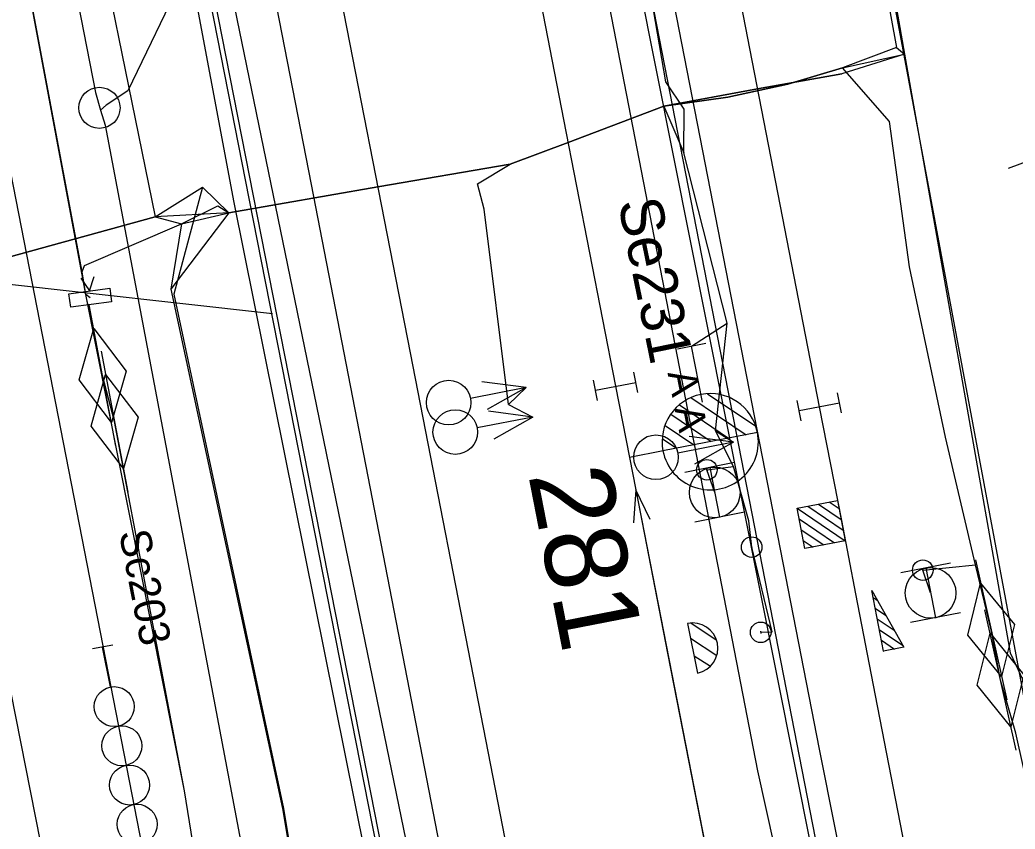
# Model space of a CAD drawing. Extents: x -545846 to -545044, y -1122650 to -1119108.
# Drawn here: x -545690.73 to -545666.54, y -1119398.54 to -1119378.88 of the extents above; entities that cross this region are included whole.
import ezdxf

# ---------------------------------------------------------------- set-up
doc = ezdxf.new("R2010")
doc.units = 0
for name, color, linetype in [('osvětlené plochy-hodnota-obrys', 7, 'Continuous'), ('Vrstva 1', 7, 'Continuous'), ('Vrstva 1 - Koleje', 7, 'Continuous'), ('Vrstva 2 - Vyhybky', 7, 'Continuous'), ('Vrstva 26', 7, 'Continuous'), ('Vrstva 27', 7, 'Continuous'), ('Vrstva 28 - zabzar', 7, 'Continuous'), ('Vrstva 3 - Lisy - Pocitaci body', 7, 'Continuous'), ('Vrstva 31', 7, 'Continuous'), ('Vrstva 32', 7, 'Continuous'), ('Vrstva 33 - prvky sdelzar', 7, 'Continuous'), ('Vrstva 35', 7, 'Continuous'), ('Vrstva 4 - Teren - stezky - prechody - plochy', 7, 'Continuous'), ('Vrstva 43', 7, 'Continuous'), ('Vrstva 44', 7, 'Continuous'), ('Vrstva 6', 7, 'Continuous'), ('Vrstva 6 - Navesti', 7, 'Continuous'), ('Vrstva 63', 7, 'Continuous')]:
    doc.layers.add(name, color=color, linetype=linetype)

msp = doc.modelspace()

# ---------------------------------------------------------------- linework, layer by layer
at = {"layer": 'osvětlené plochy-hodnota-obrys'}
for points in [[(-545700.341, -1119250.428), (-545705.955, -1119221.665), (-545699.039, -1119220.315), (-545660.607, -1119425.918), (-545653.752, -1119372.856), (-545653.095, -1119348.321), (-545657.119, -1119319.988), (-545685.945, -1119192.198), (-545694.33, -1119168.5)], [(-545730.573, -1119179.645), (-545675.345, -1119462.605), (-545660.82, -1119505.941)], [(-545716.386, -1119223.717), (-545705.994, -1119221.66), (-545669.439, -1119408.759), (-545659.4, -1119462.635), (-545647.69, -1119521.347), (-545640.519, -1119558.729), (-545633.585, -1119589.698), (-545629.517, -1119613.814), (-545623.042, -1119645.057), (-545619.034, -1119667.556), (-545607.519, -1119727.517)], [(-545610.895, -1119760.665), (-545622.836, -1119699.488), (-545637.26, -1119626.872), (-545653.542, -1119543.449), (-545716.386, -1119223.717)]]:
    msp.add_lwpolyline(points, dxfattribs=at)
at = {"layer": 'Vrstva 1'}
msp.add_lwpolyline([(-545720.48, -1119243.554), (-545716.211, -1119265.458), (-545709.71, -1119298.83), (-545705.603, -1119319.946), (-545703.826, -1119329.138), (-545700.44, -1119346.499), (-545698.393, -1119357.038), (-545695.828, -1119370.213), (-545691.674, -1119391.619), (-545690.242, -1119398.846), (-545690.242, -1119398.846)], dxfattribs=at)
at = {"layer": 'Vrstva 1 - Koleje'}
for points in [[(-545681.637, -1119335.101), (-545671.298, -1119388.278), (-545670.76, -1119391.045), (-545670.414, -1119392.823), (-545669.934, -1119395.293), (-545667.967, -1119405.429), (-545666.055, -1119415.218), (-545664.157, -1119424.959), (-545662.28, -1119434.594), (-545660.571, -1119443.365), (-545656.357, -1119464.982), (-545653.314, -1119480.588), (-545652.53, -1119484.609), (-545652.377, -1119485.394)], [(-545678.788, -1119374.744), (-545677.514, -1119381.295), (-545676.249, -1119387.782), (-545675.912, -1119389.513)], [(-545683.274, -1119376.56), (-545681.242, -1119386.97), (-545679.47, -1119396.069), (-545677.244, -1119407.477), (-545675.184, -1119418.032), (-545673.045, -1119429.027), (-545670.931, -1119439.856), (-545669.293, -1119448.281), (-545667.274, -1119458.644), (-545665.203, -1119469.256), (-545663.032, -1119480.361), (-545661.358, -1119488.941), (-545659.379, -1119499.086)], [(-545675.912, -1119389.513), (-545675.759, -1119390.298), (-545671.927, -1119409.919), (-545665.915, -1119431.178), (-545662.323, -1119443.901), (-545656.357, -1119464.982), (-545652.53, -1119484.609), (-545652.377, -1119485.394)], [(-545675.912, -1119389.513), (-545675.759, -1119390.298), (-545674.983, -1119394.269), (-545671.927, -1119409.919), (-545667.706, -1119431.538), (-545665.572, -1119442.504), (-545664.599, -1119447.508), (-545663.149, -1119454.944), (-545661.077, -1119465.581), (-545659.119, -1119475.61), (-545657.219, -1119485.395), (-545655.182, -1119495.829), (-545653.541, -1119504.242), (-545653.037, -1119506.841)]]:
    msp.add_lwpolyline(points, dxfattribs=at)
at = {"layer": 'Vrstva 2 - Vyhybky'}
for p, q in [((-545674.016, -1119387.961), (-545672.841, -1119388.752)), ((-545674.699, -1119388.233), (-545673.5, -1119389.041)), ((-545674.416, -1119388.057), (-545673.078, -1119388.959)), ((-545674.906, -1119388.46), (-545673.923, -1119389.124)), ((-545672.798, -1119388.904), (-545675.097, -1119389.352)), ((-545675.047, -1119388.731), (-545674.344, -1119389.205)), ((-545672.798, -1119388.904), (-545672.798, -1119388.904)), ((-545675.114, -1119389.053), (-545674.767, -1119389.287)), ((-545675.096, -1119389.352), (-545675.912, -1119389.513))]:
    msp.add_line(p, q, dxfattribs=at)
for points in [[(-545675.912, -1119389.513), (-545675.759, -1119390.298), (-545671.927, -1119409.919), (-545667.706, -1119431.538)], [(-545675.408, -1119391.017), (-545675.759, -1119390.298), (-545675.814, -1119391.096)]]:
    msp.add_lwpolyline(points, dxfattribs=at)
for centre, radius, start, end in [((-545673.948, -1119389.128), 1.171, 11.0504, 191.0112), ((-545673.948, -1119389.129), 1.17, 190.9608, 11.4304)]:
    msp.add_arc(centre, radius, start, end, dxfattribs=at)
at = {"layer": 'Vrstva 26'}
for points in [[(-545669.284, -1119291.014), (-545671.67, -1119294.536), (-545673.507, -1119295.057), (-545676.739, -1119296.191), (-545682.284, -1119297.916), (-545682.944, -1119298.121), (-545684.526, -1119298.831), (-545685.076, -1119301.217), (-545681.518, -1119318.897), (-545678.885, -1119332.432), (-545675.639, -1119348.357), (-545675.262, -1119352.744), (-545674.052, -1119356.623), (-545671.95, -1119367.037), (-545671.035, -1119371.566), (-545669.914, -1119375.777), (-545669.221, -1119379.711), (-545666.658, -1119394.257), (-545666.038, -1119395.572), (-545665.51, -1119396.73), (-545664.32, -1119397.6), (-545664.49, -1119398.35), (-545664.917, -1119398.423)], [(-545669.221, -1119379.711), (-545670.748, -1119380.192), (-545672.801, -1119380.55), (-545675.08, -1119380.973), (-545677.404, -1119381.86), (-545678.81, -1119382.38), (-545682.029, -1119382.937), (-545685.653, -1119383.563), (-545687.063, -1119385.421)], [(-545685.653, -1119383.563), (-545682.029, -1119382.937), (-545678.81, -1119382.38), (-545677.404, -1119381.86), (-545675.08, -1119380.973), (-545672.801, -1119380.55), (-545670.748, -1119380.192)], [(-545685.653, -1119383.563), (-545687.442, -1119383.663), (-545698.546, -1119386.715), (-545701.735, -1119388.211)], [(-545685.653, -1119383.563), (-545687.442, -1119383.663), (-545698.546, -1119386.715)], [(-545687.063, -1119385.421), (-545684.343, -1119398.043), (-545682.972, -1119406.266), (-545682.725, -1119408.63), (-545682.477, -1119411.005), (-545680.726, -1119416.47), (-545676.513, -1119436.442), (-545675.693, -1119440.376), (-545675.368, -1119441.242), (-545685.239, -1119443.159), (-545691.11, -1119444.524)]]:
    msp.add_lwpolyline(points, dxfattribs=at)
at = {"layer": 'Vrstva 27'}
for p, q in [((-545689.537, -1119385.535), (-545689.535, -1119385.531)), ((-545674.035, -1119389.785), (-545674.025, -1119389.835)), ((-545672.945, -1119391.665), (-545672.935, -1119391.715)), ((-545668.774, -1119392.274), (-545668.786, -1119392.226)), ((-545672.725, -1119393.735), (-545672.715, -1119393.785))]:
    msp.add_line(p, q, dxfattribs=at)
msp.add_lwpolyline([(-545689.252, -1119385.157), (-545689.042, -1119385.465), (-545688.922, -1119385.112)], dxfattribs=at)
msp.add_lwpolyline([(-545689.538, -1119385.532), (-545688.547, -1119385.398), (-545688.502, -1119385.728), (-545689.493, -1119385.862)], close=True, dxfattribs=at)
for centre in [(-545674.03, -1119389.81), (-545672.94, -1119391.69), (-545668.78, -1119392.25), (-545672.72, -1119393.76)]:
    msp.add_circle(centre, 0.25, dxfattribs=at)
at = {"layer": 'Vrstva 28 - zabzar'}
for p, q in [((-545689.02, -1119385.63), (-545689.13, -1119385.55)), ((-545688.395, -1119389.235), (-545689.045, -1119385.805)), ((-545674.4, -1119386.81), (-545673.54, -1119386.25)), ((-545689.292, -1119387.628), (-545688.937, -1119386.377)), ((-545688.937, -1119386.377), (-545688.148, -1119387.412)), ((-545688.755, -1119386.925), (-545688.105, -1119390.355)), ((-545689.002, -1119388.748), (-545688.647, -1119387.497)), ((-545688.647, -1119387.497), (-545687.858, -1119388.532)), ((-545688.148, -1119387.412), (-545688.503, -1119388.663)), ((-545688.503, -1119388.663), (-545689.292, -1119387.628)), ((-545687.858, -1119388.532), (-545688.213, -1119389.783)), ((-545688.213, -1119389.783), (-545689.002, -1119388.748)), ((-545673.82, -1119388.86), (-545673.38, -1119389.14)), ((-545667.5, -1119391.996), (-545666.74, -1119395.404)), ((-545667.688, -1119393.827), (-545667.374, -1119392.564)), ((-545667.374, -1119392.564), (-545666.552, -1119393.573)), ((-545666.51, -1119396.624), (-545667.27, -1119393.216)), ((-545667.458, -1119395.047), (-545667.144, -1119393.784)), ((-545667.144, -1119393.784), (-545666.322, -1119394.793)), ((-545666.552, -1119393.573), (-545666.866, -1119394.836)), ((-545666.866, -1119394.836), (-545667.688, -1119393.827)), ((-545666.322, -1119394.793), (-545666.636, -1119396.056)), ((-545666.636, -1119396.056), (-545667.458, -1119395.047))]:
    msp.add_line(p, q, dxfattribs=at)
for points in [[(-545672.72, -1119393.76), (-545672.44, -1119393.75), (-545672.94, -1119391.69), (-545673.01, -1119391.05), (-545673.38, -1119389.73), (-545673.82, -1119388.86), (-545673.54, -1119386.25), (-545674.59, -1119382.11), (-545674.58, -1119381.05), (-545675.03, -1119380.38), (-545676.38, -1119372.48), (-545676.99, -1119369.46), (-545677.56, -1119369.53)], [(-545689.22, -1119385), (-545692.02, -1119370.12)], [(-545689.22, -1119385), (-545689.16, -1119384.85), (-545686.8, -1119383.83), (-545685.92, -1119383.4), (-545685.653, -1119383.563), (-545682.029, -1119382.937), (-545678.81, -1119382.38), (-545677.404, -1119381.86), (-545675.08, -1119380.973), (-545673.516, -1119380.759), (-545672.065, -1119380.44), (-545670.73, -1119380.04)], [(-545651.39, -1119432.58), (-545651.46, -1119431.88), (-545650.93, -1119431.94), (-545650.09, -1119432.05), (-545649.94, -1119430.41), (-545650.19, -1119430.33), (-545657.8, -1119431.19), (-545660.08, -1119431.44), (-545661.89, -1119421.17), (-545664.18, -1119409.73), (-545664.27, -1119408.03), (-545665.37, -1119401.36), (-545666.52, -1119396.21), (-545666.89, -1119394.92), (-545667.12, -1119393.7), (-545667.5, -1119392.12), (-545668.23, -1119389.02), (-545669.1, -1119384.88), (-545669.59, -1119381.35), (-545670.73, -1119380.04)], [(-545675.08, -1119380.973), (-545674.59, -1119382.11)], [(-545678.85, -1119388.22), (-545679.44, -1119383.48), (-545679.61, -1119382.86), (-545678.81, -1119382.38)], [(-545676.93, -1119448.23), (-545679.71, -1119434.6), (-545680.78, -1119428.7), (-545683.44, -1119416.1), (-545684.36, -1119411.01), (-545685.82, -1119403.23), (-545686.73, -1119397.61), (-545688.43, -1119388.64), (-545688.72, -1119387.52), (-545689.13, -1119385.55), (-545689.22, -1119385)], [(-545678.42, -1119387.81), (-545678.85, -1119388.22), (-545678.26, -1119388.53)], [(-545673.84, -1119390.36), (-545674.03, -1119389.81), (-545673.38, -1119389.73)], [(-545668.59, -1119392.8), (-545668.78, -1119392.25), (-545667.5, -1119392.12)]]:
    msp.add_lwpolyline(points, dxfattribs=at)
at = {"layer": 'Vrstva 3 - Lisy - Pocitaci body'}
for p, q in [((-545675.71, -1119387.932), (-545675.806, -1119387.441)), ((-545678.42, -1119387.81), (-545679.502, -1119387.67)), ((-545676.692, -1119388.123), (-545676.788, -1119387.632)), ((-545676.74, -1119387.878), (-545675.758, -1119387.686)), ((-545678.42, -1119387.81), (-545679.774, -1119388.075)), ((-545678.42, -1119387.81), (-545679.369, -1119388.347)), ((-545670.759, -1119388.428), (-545670.855, -1119387.937)), ((-545671.741, -1119388.619), (-545671.837, -1119388.128)), ((-545671.789, -1119388.373), (-545670.807, -1119388.183)), ((-545678.26, -1119388.53), (-545679.342, -1119388.389)), ((-545678.26, -1119388.53), (-545679.615, -1119388.794)), ((-545678.26, -1119388.53), (-545679.21, -1119389.066)), ((-545673.38, -1119389.14), (-545674.735, -1119389.404)), ((-545673.38, -1119389.14), (-545674.462, -1119388.999)), ((-545673.38, -1119389.14), (-545674.33, -1119389.676)), ((-545673.356, -1119389.636), (-545674.564, -1119389.876)), ((-545673.96, -1119389.756), (-545673.72, -1119390.964)), ((-545671.316, -1119390.644), (-545670.766, -1119391.015)), ((-545671.056, -1119390.593), (-545670.816, -1119390.755)), ((-545673.116, -1119390.844), (-545674.324, -1119391.084)), ((-545671.837, -1119390.745), (-545670.665, -1119391.536)), ((-545671.577, -1119390.695), (-545670.715, -1119391.276)), ((-545671.786, -1119391.005), (-545670.925, -1119391.586)), ((-545671.736, -1119391.266), (-545671.185, -1119391.637)), ((-545671.685, -1119391.526), (-545671.445, -1119391.688)), ((-545668.104, -1119392.077), (-545669.313, -1119392.314)), ((-545668.708, -1119392.195), (-545668.472, -1119393.405)), ((-545669.989, -1119392.913), (-545669.89, -1119392.979)), ((-545669.938, -1119393.173), (-545669.684, -1119393.344)), ((-545667.867, -1119393.286), (-545669.076, -1119393.523)), ((-545674.502, -1119393.545), (-545674.255, -1119394.752)), ((-545674.419, -1119393.533), (-545673.805, -1119393.941)), ((-545669.888, -1119393.433), (-545669.478, -1119393.709)), ((-545669.837, -1119393.694), (-545669.272, -1119394.075)), ((-545674.429, -1119393.9), (-545673.79, -1119394.322)), ((-545669.786, -1119393.954), (-545669.469, -1119394.167)), ((-545669.736, -1119394.214), (-545669.729, -1119394.218)), ((-545674.342, -1119394.328), (-545673.945, -1119394.585)), ((-545674.255, -1119394.752), (-545674.255, -1119394.752))]:
    msp.add_line(p, q, dxfattribs=at)
msp.add_lwpolyline([(-545670.855, -1119390.554), (-545670.665, -1119391.536), (-545671.646, -1119391.727), (-545671.837, -1119390.745)], close=True, dxfattribs=at)
msp.add_lwpolyline([(-545670.021, -1119392.747), (-545669.244, -1119394.124), (-545669.735, -1119394.219), (-545670.021, -1119392.747)], dxfattribs=at)
for centre, radius in [((-545680.307, -1119388.177), 0.542), ((-545680.147, -1119388.895), 0.542), ((-545675.267, -1119389.505), 0.542), ((-545673.839, -1119390.362), 0.616), ((-545668.589, -1119392.802), 0.616)]:
    msp.add_circle(centre, radius, dxfattribs=at)
for start, end in [(11.5346, 101.5346), (281.5346, 11.5346)]:
    msp.add_arc((-545674.378, -1119394.148), 0.616, start, end, dxfattribs=at)
at = {"layer": 'Vrstva 31'}
for points in [[(-545705.72, -1119289.965), (-545705.666, -1119289.946), (-545703.957, -1119291.398), (-545703.473, -1119295.232), (-545704.09, -1119296.872), (-545702.861, -1119304.32), (-545698.681, -1119324.981), (-545696.502, -1119336.531), (-545693.744, -1119351.629), (-545691.156, -1119365.479), (-545687.442, -1119383.663), (-545686.29, -1119382.94)], [(-545669.783, -1119291.131), (-545672.206, -1119293.898), (-545672.878, -1119294.726), (-545676.721, -1119296.165), (-545682.968, -1119298.105), (-545684.562, -1119298.802), (-545685.271, -1119301.217), (-545681.902, -1119318.023), (-545679.037, -1119332.697), (-545675.878, -1119348.362), (-545675.455, -1119352.785), (-545674.365, -1119356.614), (-545673.497, -1119359.701), (-545672.189, -1119367.114), (-545671.293, -1119371.554), (-545670.112, -1119375.778), (-545669.417, -1119379.549), (-545670.73, -1119380.04), (-545672.065, -1119380.44), (-545673.516, -1119380.759), (-545675.08, -1119380.973)], [(-545677.97, -1119443.43), (-545679.71, -1119434.6), (-545680.78, -1119428.7), (-545683.44, -1119416.1), (-545684.36, -1119411.01), (-545685.82, -1119403.23), (-545686.73, -1119397.61), (-545689.13, -1119385.55), (-545689.22, -1119385), (-545692.02, -1119370.12)], [(-545669.914, -1119375.777), (-545669.221, -1119379.711), (-545666.658, -1119394.257), (-545666.038, -1119395.572), (-545664.679, -1119396.306), (-545663.74, -1119396.46), (-545655, -1119395.26), (-545648.32, -1119395.5), (-545646.036, -1119392.519), (-545638.834, -1119390.976), (-545637.989, -1119391.804), (-545637.617, -1119393.956), (-545636.118, -1119401.068)], [(-545686.8, -1119383.83), (-545685.653, -1119383.563), (-545682.029, -1119382.937), (-545678.81, -1119382.38), (-545677.404, -1119381.86), (-545677.404, -1119381.86), (-545675.08, -1119380.973), (-545673.516, -1119380.759), (-545672.065, -1119380.44), (-545670.73, -1119380.04), (-545669.221, -1119379.711)], [(-545669.417, -1119379.549), (-545669.221, -1119379.711), (-545666.658, -1119394.257), (-545666.038, -1119395.572)], [(-545675.08, -1119380.973), (-545677.404, -1119381.86), (-545678.81, -1119382.38), (-545682.029, -1119382.937), (-545685.653, -1119383.563), (-545686.29, -1119382.94), (-545686.991, -1119385.539), (-545684.322, -1119398.039), (-545682.95, -1119406.261), (-545682.441, -1119410.994), (-545680.712, -1119416.465), (-545675.599, -1119440.373), (-545674.73, -1119441.437), (-545675.364, -1119441.292), (-545685.239, -1119443.209), (-545690.839, -1119444.56)], [(-545725.735, -1119411.961), (-545722.48, -1119408.5), (-545719.46, -1119405.92), (-545717.08, -1119402.17), (-545714.88, -1119397.08), (-545714.21, -1119393.19), (-545714.49, -1119390.6), (-545708.48, -1119388.84), (-545703.45, -1119389.15), (-545701.491, -1119387.522), (-545698.546, -1119386.715), (-545687.442, -1119383.663), (-545686.8, -1119383.83)], [(-545686.8, -1119383.83), (-545687.063, -1119385.421), (-545684.343, -1119398.043), (-545682.95, -1119406.261), (-545682.477, -1119411.005), (-545680.726, -1119416.47), (-545676.513, -1119436.442), (-545675.599, -1119440.373), (-545674.73, -1119441.437), (-545674.246, -1119445.902), (-545673.636, -1119447.545)]]:
    msp.add_lwpolyline(points, dxfattribs=at)
at = {"layer": 'Vrstva 32'}
msp.add_lwpolyline([(-545681.68, -1119491.62), (-545683.99, -1119485.87), (-545685.98, -1119481.96), (-545687.53, -1119476.16), (-545688.66, -1119471.01), (-545689.78, -1119464.16), (-545689.5, -1119458.09), (-545688.39, -1119454.35), (-545688.08, -1119454.15), (-545684.37, -1119450.24), (-545683.81, -1119449.95), (-545681.81, -1119449.43), (-545678.89, -1119448.97), (-545677.49, -1119448.61), (-545676.93, -1119448.23), (-545679.71, -1119434.6), (-545680.78, -1119428.7), (-545683.44, -1119416.1), (-545684.36, -1119411.01), (-545685.82, -1119403.23), (-545686.73, -1119397.61), (-545689.13, -1119385.55), (-545692.02, -1119370.12)], dxfattribs=at)
at = {"layer": 'Vrstva 33 - prvky sdelzar'}
msp.add_lwpolyline([(-545670.73, -1119380.04), (-545672.065, -1119380.44), (-545673.516, -1119380.759), (-545675.08, -1119380.973), (-545677.404, -1119381.86), (-545678.81, -1119382.38), (-545682.029, -1119382.937), (-545685.653, -1119383.563), (-545687.442, -1119383.663), (-545698.546, -1119386.715)], dxfattribs=at)
at = {"layer": 'Vrstva 35'}
for points in [[(-545675.08, -1119380.973), (-545673.516, -1119380.759), (-545672.065, -1119380.44), (-545670.73, -1119380.04)], [(-545686.8, -1119383.83), (-545685.653, -1119383.563), (-545682.029, -1119382.937), (-545678.81, -1119382.38), (-545677.404, -1119381.86), (-545675.08, -1119380.973)]]:
    msp.add_lwpolyline(points, dxfattribs=at)
at = {"layer": 'Vrstva 4 - Teren - stezky - prechody - plochy'}
for points in [[(-545706.355, -1119218.803), (-545707.51, -1119218.932), (-545702.452, -1119245.262), (-545692.085, -1119298.133), (-545681.28, -1119353.378), (-545672.8, -1119397.126), (-545671.145, -1119404.595), (-545668.049, -1119418.039), (-545667.069, -1119417.83)], [(-545706.355, -1119218.803), (-545705.856, -1119218.828), (-545700.854, -1119244.947), (-545690.54, -1119297.817), (-545679.814, -1119352.936), (-545671.301, -1119396.597), (-545667.069, -1119417.83)], [(-545663.732, -1119493.482), (-545662.217, -1119493.136), (-545662.27, -1119492.38), (-545664.76, -1119479.724), (-545673.059, -1119437.391), (-545683.638, -1119382.878), (-545688.896, -1119355.974), (-545694.44, -1119327.554), (-545697.827, -1119310.185), (-545704.93, -1119274.138), (-545706.059, -1119274.463)], [(-545663.732, -1119493.482), (-545663.86, -1119492.962), (-545666.439, -1119479.174), (-545674.481, -1119437.861), (-545674.838, -1119435.68), (-545679.752, -1119410.669), (-545685.159, -1119383.219), (-545690.428, -1119356.383), (-545695.755, -1119327.999), (-545699.195, -1119310.645), (-545701.333, -1119300.523), (-545702.296, -1119295.62), (-545704.229, -1119285.397), (-545706.059, -1119274.463)], [(-545674.838, -1119435.68), (-545676.549, -1119430.017), (-545679.882, -1119411.316), (-545685.521, -1119383.317), (-545690.583, -1119356.379), (-545695.903, -1119329.098), (-545699.555, -1119310.884), (-545701.333, -1119300.523)], [(-545674.838, -1119435.68), (-545679.752, -1119410.669), (-545685.159, -1119383.219), (-545690.428, -1119356.383), (-545695.755, -1119327.999), (-545699.195, -1119310.645), (-545701.333, -1119300.523)]]:
    msp.add_lwpolyline(points, dxfattribs=at)
at = {"layer": 'Vrstva 43'}
msp.add_circle((-545688.797, -1119381.015), 0.5, dxfattribs=at)
at = {"layer": 'Vrstva 44'}
for points in [[(-545698.387, -1119332.167), (-545688.892, -1119380.643), (-545688.773, -1119381.07), (-545688.658, -1119381.436), (-545684.204, -1119404.98), (-545684.3, -1119405.214), (-545684.473, -1119405.424), (-545695.821, -1119407.408), (-545696.222, -1119407.647), (-545696.303, -1119408.062), (-545686.856, -1119457.258), (-545686.828, -1119457.471), (-545686.717, -1119457.756), (-545678.249, -1119507.566)], [(-545659.224, -1119462.954), (-545669.377, -1119409.578), (-545676.105, -1119375.826)], [(-545685.693, -1119377.451), (-545686.049, -1119377.656), (-545686.75, -1119377.792), (-545688.105, -1119380.598), (-545688.634, -1119380.95), (-545688.773, -1119381.07)], [(-545668.174, -1119464.967), (-545678.695, -1119411.658), (-545685.683, -1119377.701), (-545685.693, -1119377.451)]]:
    msp.add_lwpolyline(points, dxfattribs=at)
at = {"layer": 'Vrstva 6'}
for p, q in [((-545688.475, -1119394.069), (-545688.966, -1119394.164)), ((-545688.531, -1119395.088), (-545688.72, -1119394.117))]:
    msp.add_line(p, q, dxfattribs=at)
for centre in [(-545688.438, -1119395.565), (-545688.252, -1119396.518), (-545688.066, -1119397.471), (-545687.881, -1119398.424)]:
    msp.add_circle(centre, 0.486, dxfattribs=at)
at = {"layer": 'Vrstva 6 - Navesti'}
for p, q in [((-545674.057, -1119386.743), (-545674.743, -1119386.877)), ((-545674.134, -1119388.17), (-545674.4, -1119386.81))]:
    msp.add_line(p, q, dxfattribs=at)
at = {"layer": 'Vrstva 63'}
for p, q in [((-545574.476, -1119347.748), (-545666.705, -1119382.49)), ((-545684.593, -1119386.018), (-545726.451, -1119381.392))]:
    msp.add_line(p, q, dxfattribs=at)

# ---------------------------------------------------------------- texts
at = {"layer": 'Vrstva 2 - Vyhybky'}
msp.add_text('281', height=2, rotation=281.0291, dxfattribs=at).set_placement((-545678.374, -1119389.93))
at = {"layer": 'Vrstva 6'}
msp.add_text('Sc203', height=0.75, rotation=281.0181, dxfattribs=at).set_placement((-545688.325, -1119391.336))
at = {"layer": 'Vrstva 6 - Navesti'}
for s, height, rotation, p in [('Se231', 1.05, 281.5063, (-545676.195, -1119383.308)), ('  A A ', 0.7, 281.0739, (-545675.087, -1119386.944))]:
    msp.add_text(s, height=height, rotation=rotation, dxfattribs=at).set_placement(p)

doc.saveas('drawing.dxf')
